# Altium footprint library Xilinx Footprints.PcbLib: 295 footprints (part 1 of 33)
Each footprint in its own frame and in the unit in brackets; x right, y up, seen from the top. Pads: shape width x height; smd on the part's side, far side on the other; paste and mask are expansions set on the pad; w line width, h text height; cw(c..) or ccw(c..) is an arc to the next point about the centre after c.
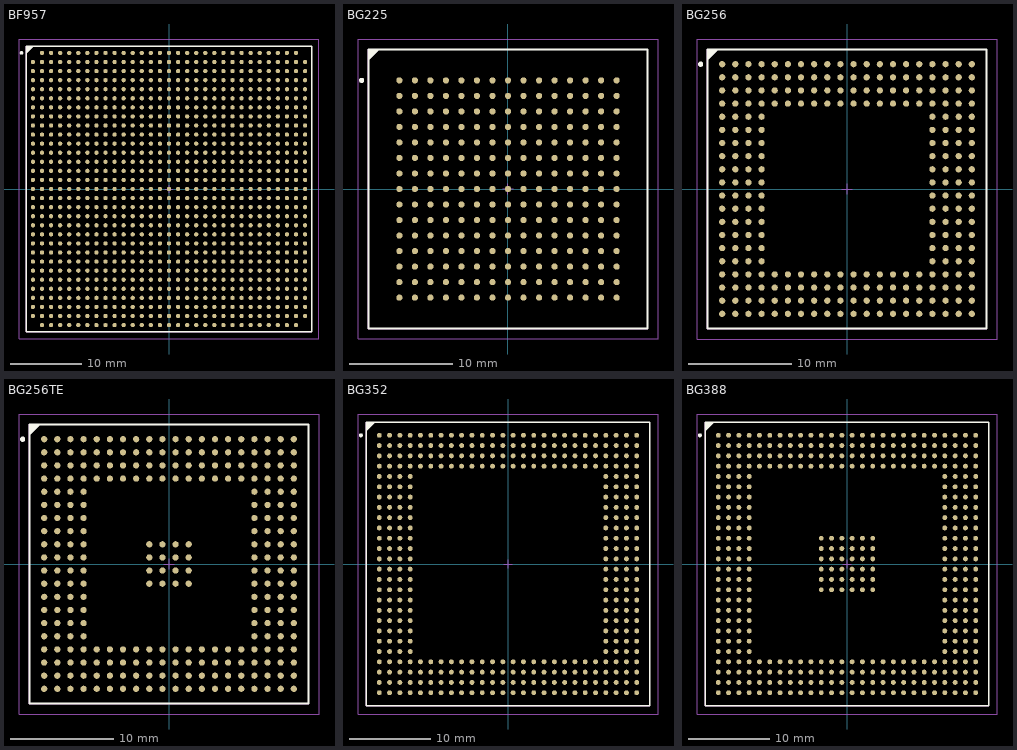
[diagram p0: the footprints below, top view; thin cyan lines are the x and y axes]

## BF957 [mm] "957-Ball Plastic Flip Chip Ball Grid Array (BF957)"
height 3.5
pads (957):
  round 0.6 smd: A2(-17.78,19.05) A3(-16.51,19.05) A4(-15.24,19.05) A5(-13.97,19.05) A6(-12.7,19.05) A7(-11.43,19.05) A8(-10.16,19.05) A9(-8.89,19.05) A10(-7.62,19.05) A11(-6.35,19.05) A12(-5.08,19.05) A13(-3.81,19.05) A14(-2.54,19.05) A15(-1.27,19.05) A16(0,19.05) A17(1.27,19.05) A18(2.54,19.05) A19(3.81,19.05) A20(5.08,19.05) A21(6.35,19.05) A22(7.62,19.05) A23(8.89,19.05) A24(10.16,19.05) A25(11.43,19.05) A26(12.7,19.05) A27(13.97,19.05) A28(15.24,19.05) A29(16.51,19.05) A30(17.78,19.05) AA1(-19.05,-6.35) AA2(-17.78,-6.35) AA3(-16.51,-6.35) AA4(-15.24,-6.35) AA5(-13.97,-6.35) AA6(-12.7,-6.35) AA7(-11.43,-6.35) AA8(-10.16,-6.35) AA9(-8.89,-6.35) AA10(-7.62,-6.35) AA11(-6.35,-6.35) AA12(-5.08,-6.35) AA13(-3.81,-6.35) AA14(-2.54,-6.35) AA15(-1.27,-6.35) AA16(0,-6.35) AA17(1.27,-6.35) AA18(2.54,-6.35) AA19(3.81,-6.35) AA20(5.08,-6.35) AA21(6.35,-6.35) AA22(7.62,-6.35) AA23(8.89,-6.35) AA24(10.16,-6.35) AA25(11.43,-6.35) AA26(12.7,-6.35) AA27(13.97,-6.35) AA28(15.24,-6.35) AA29(16.51,-6.35) AA30(17.78,-6.35) AA31(19.05,-6.35) AB1(-19.05,-7.62) AB2(-17.78,-7.62) AB3(-16.51,-7.62) AB4(-15.24,-7.62) AB5(-13.97,-7.62) AB6(-12.7,-7.62) AB7(-11.43,-7.62) AB8(-10.16,-7.62) AB9(-8.89,-7.62) AB10(-7.62,-7.62) AB11(-6.35,-7.62) AB12(-5.08,-7.62) AB13(-3.81,-7.62) AB14(-2.54,-7.62) AB15(-1.27,-7.62) AB16(0,-7.62) AB17(1.27,-7.62) AB18(2.54,-7.62) AB19(3.81,-7.62) AB20(5.08,-7.62) AB21(6.35,-7.62) AB22(7.62,-7.62) AB23(8.89,-7.62) AB24(10.16,-7.62) AB25(11.43,-7.62) AB26(12.7,-7.62) AB27(13.97,-7.62) AB28(15.24,-7.62) AB29(16.51,-7.62) AB30(17.78,-7.62) AB31(19.05,-7.62) AC1(-19.05,-8.89) AC2(-17.78,-8.89) AC3(-16.51,-8.89) AC4(-15.24,-8.89) AC5(-13.97,-8.89) AC6(-12.7,-8.89) AC7(-11.43,-8.89) AC8(-10.16,-8.89) AC9(-8.89,-8.89) AC10(-7.62,-8.89) AC11(-6.35,-8.89) AC12(-5.08,-8.89) AC13(-3.81,-8.89) AC14(-2.54,-8.89) AC15(-1.27,-8.89) AC16(0,-8.89) AC17(1.27,-8.89) AC18(2.54,-8.89) AC19(3.81,-8.89) AC20(5.08,-8.89) AC21(6.35,-8.89) AC22(7.62,-8.89) AC23(8.89,-8.89) AC24(10.16,-8.89) AC25(11.43,-8.89) AC26(12.7,-8.89) AC27(13.97,-8.89) AC28(15.24,-8.89) AC29(16.51,-8.89) AC30(17.78,-8.89) AC31(19.05,-8.89) AD1(-19.05,-10.16) AD2(-17.78,-10.16) AD3(-16.51,-10.16) AD4(-15.24,-10.16) AD5(-13.97,-10.16) AD6(-12.7,-10.16) AD7(-11.43,-10.16) AD8(-10.16,-10.16) AD9(-8.89,-10.16) AD10(-7.62,-10.16) AD11(-6.35,-10.16) AD12(-5.08,-10.16) AD13(-3.81,-10.16) AD14(-2.54,-10.16) AD15(-1.27,-10.16) AD16(0,-10.16) AD17(1.27,-10.16) AD18(2.54,-10.16) AD19(3.81,-10.16) AD20(5.08,-10.16) AD21(6.35,-10.16) AD22(7.62,-10.16) AD23(8.89,-10.16) AD24(10.16,-10.16) AD25(11.43,-10.16) AD26(12.7,-10.16) AD27(13.97,-10.16) AD28(15.24,-10.16) AD29(16.51,-10.16) AD30(17.78,-10.16) AD31(19.05,-10.16) AE1(-19.05,-11.43) AE2(-17.78,-11.43) AE3(-16.51,-11.43) AE4(-15.24,-11.43) AE5(-13.97,-11.43) AE6(-12.7,-11.43) AE7(-11.43,-11.43) AE8(-10.16,-11.43) AE9(-8.89,-11.43) AE10(-7.62,-11.43) AE11(-6.35,-11.43) AE12(-5.08,-11.43) AE13(-3.81,-11.43) AE14(-2.54,-11.43) AE15(-1.27,-11.43) AE16(0,-11.43) AE17(1.27,-11.43) AE18(2.54,-11.43) AE19(3.81,-11.43) AE20(5.08,-11.43) AE21(6.35,-11.43) AE22(7.62,-11.43) AE23(8.89,-11.43) AE24(10.16,-11.43) AE25(11.43,-11.43) AE26(12.7,-11.43) AE27(13.97,-11.43) AE28(15.24,-11.43) AE29(16.51,-11.43) AE30(17.78,-11.43) AE31(19.05,-11.43) AF1(-19.05,-12.7) AF2(-17.78,-12.7) AF3(-16.51,-12.7) AF4(-15.24,-12.7) AF5(-13.97,-12.7) AF6(-12.7,-12.7) AF7(-11.43,-12.7) AF8(-10.16,-12.7) AF9(-8.89,-12.7) AF10(-7.62,-12.7) AF11(-6.35,-12.7) AF12(-5.08,-12.7) AF13(-3.81,-12.7) AF14(-2.54,-12.7) AF15(-1.27,-12.7) AF16(0,-12.7) AF17(1.27,-12.7) AF18(2.54,-12.7) AF19(3.81,-12.7) AF20(5.08,-12.7) AF21(6.35,-12.7) AF22(7.62,-12.7) AF23(8.89,-12.7) AF24(10.16,-12.7) AF25(11.43,-12.7) AF26(12.7,-12.7) AF27(13.97,-12.7) AF28(15.24,-12.7) AF29(16.51,-12.7) AF30(17.78,-12.7) AF31(19.05,-12.7) AG1(-19.05,-13.97) AG2(-17.78,-13.97) AG3(-16.51,-13.97) AG4(-15.24,-13.97) AG5(-13.97,-13.97) AG6(-12.7,-13.97) AG7(-11.43,-13.97) AG8(-10.16,-13.97) AG9(-8.89,-13.97) AG10(-7.62,-13.97) AG11(-6.35,-13.97) AG12(-5.08,-13.97) AG13(-3.81,-13.97) AG14(-2.54,-13.97) AG15(-1.27,-13.97) AG16(0,-13.97) AG17(1.27,-13.97) AG18(2.54,-13.97) AG19(3.81,-13.97) AG20(5.08,-13.97) AG21(6.35,-13.97) AG22(7.62,-13.97) AG23(8.89,-13.97) AG24(10.16,-13.97) AG25(11.43,-13.97) AG26(12.7,-13.97) AG27(13.97,-13.97) AG28(15.24,-13.97) AG29(16.51,-13.97) AG30(17.78,-13.97) AG31(19.05,-13.97) AH1(-19.05,-15.24) AH2(-17.78,-15.24) AH3(-16.51,-15.24) AH4(-15.24,-15.24) AH5(-13.97,-15.24) AH6(-12.7,-15.24) AH7(-11.43,-15.24) AH8(-10.16,-15.24) AH9(-8.89,-15.24) AH10(-7.62,-15.24) AH11(-6.35,-15.24) AH12(-5.08,-15.24) AH13(-3.81,-15.24) AH14(-2.54,-15.24) AH15(-1.27,-15.24) AH16(0,-15.24) AH17(1.27,-15.24) AH18(2.54,-15.24) AH19(3.81,-15.24) AH20(5.08,-15.24) AH21(6.35,-15.24) AH22(7.62,-15.24) AH23(8.89,-15.24) AH24(10.16,-15.24) AH25(11.43,-15.24) AH26(12.7,-15.24) AH27(13.97,-15.24) AH28(15.24,-15.24) AH29(16.51,-15.24) AH30(17.78,-15.24) AH31(19.05,-15.24) AJ1(-19.05,-16.51) AJ2(-17.78,-16.51) AJ3(-16.51,-16.51) AJ4(-15.24,-16.51) AJ5(-13.97,-16.51) AJ6(-12.7,-16.51) AJ7(-11.43,-16.51) AJ8(-10.16,-16.51) AJ9(-8.89,-16.51) AJ10(-7.62,-16.51) AJ11(-6.35,-16.51) AJ12(-5.08,-16.51) AJ13(-3.81,-16.51) AJ14(-2.54,-16.51) AJ15(-1.27,-16.51) AJ16(0,-16.51) AJ17(1.27,-16.51) AJ18(2.54,-16.51) AJ19(3.81,-16.51) AJ20(5.08,-16.51) AJ21(6.35,-16.51) AJ22(7.62,-16.51) AJ23(8.89,-16.51) AJ24(10.16,-16.51) AJ25(11.43,-16.51) AJ26(12.7,-16.51) AJ27(13.97,-16.51) AJ28(15.24,-16.51) AJ29(16.51,-16.51) AJ30(17.78,-16.51) AJ31(19.05,-16.51) AK1(-19.05,-17.78) AK2(-17.78,-17.78) AK3(-16.51,-17.78) AK4(-15.24,-17.78) AK5(-13.97,-17.78) AK6(-12.7,-17.78) AK7(-11.43,-17.78) AK8(-10.16,-17.78) AK9(-8.89,-17.78) AK10(-7.62,-17.78) AK11(-6.35,-17.78) AK12(-5.08,-17.78) AK13(-3.81,-17.78) AK14(-2.54,-17.78) AK15(-1.27,-17.78) AK16(0,-17.78) AK17(1.27,-17.78) AK18(2.54,-17.78) AK19(3.81,-17.78) AK20(5.08,-17.78) AK21(6.35,-17.78) AK22(7.62,-17.78) AK23(8.89,-17.78) AK24(10.16,-17.78) AK25(11.43,-17.78) AK26(12.7,-17.78) AK27(13.97,-17.78) AK28(15.24,-17.78) AK29(16.51,-17.78) AK30(17.78,-17.78) AK31(19.05,-17.78) AL2(-17.78,-19.05) AL3(-16.51,-19.05) AL4(-15.24,-19.05) AL5(-13.97,-19.05) AL6(-12.7,-19.05) AL7(-11.43,-19.05) AL8(-10.16,-19.05) AL9(-8.89,-19.05) AL10(-7.62,-19.05) AL11(-6.35,-19.05) AL12(-5.08,-19.05) AL13(-3.81,-19.05) AL14(-2.54,-19.05) AL15(-1.27,-19.05) AL16(0,-19.05) AL17(1.27,-19.05) AL18(2.54,-19.05) AL19(3.81,-19.05) AL20(5.08,-19.05) AL21(6.35,-19.05) AL22(7.62,-19.05) AL23(8.89,-19.05) AL24(10.16,-19.05) AL25(11.43,-19.05) AL26(12.7,-19.05) AL27(13.97,-19.05) AL28(15.24,-19.05) AL29(16.51,-19.05) AL30(17.78,-19.05) B1(-19.05,17.78) B2(-17.78,17.78) B3(-16.51,17.78) B4(-15.24,17.78) B5(-13.97,17.78) B6(-12.7,17.78) B7(-11.43,17.78) B8(-10.16,17.78) B9(-8.89,17.78) B10(-7.62,17.78) B11(-6.35,17.78) B12(-5.08,17.78) B13(-3.81,17.78) B14(-2.54,17.78) B15(-1.27,17.78) B16(0,17.78) B17(1.27,17.78) B18(2.54,17.78) B19(3.81,17.78) B20(5.08,17.78) B21(6.35,17.78) B22(7.62,17.78) B23(8.89,17.78) B24(10.16,17.78) B25(11.43,17.78) B26(12.7,17.78) B27(13.97,17.78) B28(15.24,17.78) B29(16.51,17.78) B30(17.78,17.78) B31(19.05,17.78) C1(-19.05,16.51) C2(-17.78,16.51) C3(-16.51,16.51) C4(-15.24,16.51) C5(-13.97,16.51) C6(-12.7,16.51) C7(-11.43,16.51) C8(-10.16,16.51) C9(-8.89,16.51) C10(-7.62,16.51) C11(-6.35,16.51) C12(-5.08,16.51) C13(-3.81,16.51) C14(-2.54,16.51) C15(-1.27,16.51) C16(0,16.51) C17(1.27,16.51) C18(2.54,16.51) C19(3.81,16.51) C20(5.08,16.51) C21(6.35,16.51) C22(7.62,16.51) C23(8.89,16.51) C24(10.16,16.51) C25(11.43,16.51) C26(12.7,16.51) C27(13.97,16.51) C28(15.24,16.51) C29(16.51,16.51) C30(17.78,16.51) C31(19.05,16.51) D1(-19.05,15.24) D2(-17.78,15.24) D3(-16.51,15.24) D4(-15.24,15.24) D5(-13.97,15.24) D6(-12.7,15.24) D7(-11.43,15.24) D8(-10.16,15.24) D9(-8.89,15.24) D10(-7.62,15.24) D11(-6.35,15.24) D12(-5.08,15.24) D13(-3.81,15.24) D14(-2.54,15.24) D15(-1.27,15.24) D16(0,15.24) D17(1.27,15.24) D18(2.54,15.24) D19(3.81,15.24) D20(5.08,15.24) D21(6.35,15.24) D22(7.62,15.24) D23(8.89,15.24) D24(10.16,15.24) D25(11.43,15.24) D26(12.7,15.24) D27(13.97,15.24) D28(15.24,15.24) D29(16.51,15.24) D30(17.78,15.24) D31(19.05,15.24) E1(-19.05,13.97) E2(-17.78,13.97) E3(-16.51,13.97) E4(-15.24,13.97) E5(-13.97,13.97) E6(-12.7,13.97) E7(-11.43,13.97) E8(-10.16,13.97) E9(-8.89,13.97) E10(-7.62,13.97) E11(-6.35,13.97) E12(-5.08,13.97) E13(-3.81,13.97) E14(-2.54,13.97) E15(-1.27,13.97) E16(0,13.97) E17(1.27,13.97) E18(2.54,13.97) E19(3.81,13.97) E20(5.08,13.97) E21(6.35,13.97) E22(7.62,13.97) E23(8.89,13.97) E24(10.16,13.97) E25(11.43,13.97) E26(12.7,13.97) E27(13.97,13.97) E28(15.24,13.97) E29(16.51,13.97) E30(17.78,13.97) E31(19.05,13.97) F1(-19.05,12.7) F2(-17.78,12.7) F3(-16.51,12.7) F4(-15.24,12.7) F5(-13.97,12.7) F6(-12.7,12.7) F7(-11.43,12.7) F8(-10.16,12.7) F9(-8.89,12.7) F10(-7.62,12.7) F11(-6.35,12.7) F12(-5.08,12.7) F13(-3.81,12.7) F14(-2.54,12.7) F15(-1.27,12.7) F16(0,12.7) F17(1.27,12.7) F18(2.54,12.7) F19(3.81,12.7) F20(5.08,12.7) F21(6.35,12.7) F22(7.62,12.7) F23(8.89,12.7) F24(10.16,12.7) F25(11.43,12.7) F26(12.7,12.7) F27(13.97,12.7) F28(15.24,12.7) F29(16.51,12.7) F30(17.78,12.7) F31(19.05,12.7) G1(-19.05,11.43) G2(-17.78,11.43) G3(-16.51,11.43) G4(-15.24,11.43) G5(-13.97,11.43) G6(-12.7,11.43) G7(-11.43,11.43) G8(-10.16,11.43) G9(-8.89,11.43) G10(-7.62,11.43) G11(-6.35,11.43) G12(-5.08,11.43) G13(-3.81,11.43) G14(-2.54,11.43) G15(-1.27,11.43) G16(0,11.43) G17(1.27,11.43) G18(2.54,11.43) G19(3.81,11.43) G20(5.08,11.43) G21(6.35,11.43) G22(7.62,11.43) G23(8.89,11.43) G24(10.16,11.43) G25(11.43,11.43) G26(12.7,11.43) G27(13.97,11.43) G28(15.24,11.43) G29(16.51,11.43) G30(17.78,11.43) G31(19.05,11.43) H1(-19.05,10.16) H2(-17.78,10.16) H3(-16.51,10.16) H4(-15.24,10.16) H5(-13.97,10.16) H6(-12.7,10.16) H7(-11.43,10.16) H8(-10.16,10.16) H9(-8.89,10.16) H10(-7.62,10.16) H11(-6.35,10.16) H12(-5.08,10.16) H13(-3.81,10.16) H14(-2.54,10.16) H15(-1.27,10.16) H16(0,10.16) H17(1.27,10.16) H18(2.54,10.16) H19(3.81,10.16) H20(5.08,10.16) H21(6.35,10.16) H22(7.62,10.16) H23(8.89,10.16) H24(10.16,10.16) H25(11.43,10.16) H26(12.7,10.16) H27(13.97,10.16) H28(15.24,10.16) H29(16.51,10.16) H30(17.78,10.16) H31(19.05,10.16) J1(-19.05,8.89) J2(-17.78,8.89) J3(-16.51,8.89) J4(-15.24,8.89) J5(-13.97,8.89) J6(-12.7,8.89) J7(-11.43,8.89) J8(-10.16,8.89) J9(-8.89,8.89) J10(-7.62,8.89) J11(-6.35,8.89) J12(-5.08,8.89) J13(-3.81,8.89) J14(-2.54,8.89) J15(-1.27,8.89) J16(0,8.89) J17(1.27,8.89) J18(2.54,8.89) J19(3.81,8.89) J20(5.08,8.89) J21(6.35,8.89) J22(7.62,8.89) J23(8.89,8.89) J24(10.16,8.89) J25(11.43,8.89) J26(12.7,8.89) J27(13.97,8.89) J28(15.24,8.89) J29(16.51,8.89) J30(17.78,8.89) J31(19.05,8.89) K1(-19.05,7.62) K2(-17.78,7.62) K3(-16.51,7.62) K4(-15.24,7.62) K5(-13.97,7.62) K6(-12.7,7.62) K7(-11.43,7.62) K8(-10.16,7.62) K9(-8.89,7.62) K10(-7.62,7.62) K11(-6.35,7.62) K12(-5.08,7.62) K13(-3.81,7.62) K14(-2.54,7.62) K15(-1.27,7.62) K16(0,7.62) K17(1.27,7.62) K18(2.54,7.62) K19(3.81,7.62) K20(5.08,7.62) K21(6.35,7.62) K22(7.62,7.62) K23(8.89,7.62) K24(10.16,7.62) K25(11.43,7.62) K26(12.7,7.62) K27(13.97,7.62) K28(15.24,7.62) K29(16.51,7.62) K30(17.78,7.62) K31(19.05,7.62) L1(-19.05,6.35) L2(-17.78,6.35) L3(-16.51,6.35) L4(-15.24,6.35) L5(-13.97,6.35) L6(-12.7,6.35) L7(-11.43,6.35) L8(-10.16,6.35) L9(-8.89,6.35) L10(-7.62,6.35) L11(-6.35,6.35) L12(-5.08,6.35) L13(-3.81,6.35) L14(-2.54,6.35) L15(-1.27,6.35) L16(0,6.35) L17(1.27,6.35) L18(2.54,6.35) L19(3.81,6.35) L20(5.08,6.35) L21(6.35,6.35) L22(7.62,6.35) L23(8.89,6.35) L24(10.16,6.35) L25(11.43,6.35) L26(12.7,6.35) L27(13.97,6.35) L28(15.24,6.35) L29(16.51,6.35) L30(17.78,6.35) L31(19.05,6.35) M1(-19.05,5.08) M2(-17.78,5.08) M3(-16.51,5.08) M4(-15.24,5.08) M5(-13.97,5.08) M6(-12.7,5.08) M7(-11.43,5.08) M8(-10.16,5.08) M9(-8.89,5.08) M10(-7.62,5.08) M11(-6.35,5.08) M12(-5.08,5.08) M13(-3.81,5.08) M14(-2.54,5.08) M15(-1.27,5.08) M16(0,5.08) M17(1.27,5.08) M18(2.54,5.08) M19(3.81,5.08) M20(5.08,5.08) M21(6.35,5.08) M22(7.62,5.08) M23(8.89,5.08) M24(10.16,5.08) M25(11.43,5.08) M26(12.7,5.08) M27(13.97,5.08) M28(15.24,5.08) M29(16.51,5.08) M30(17.78,5.08) M31(19.05,5.08) N1(-19.05,3.81) N2(-17.78,3.81) N3(-16.51,3.81) N4(-15.24,3.81) N5(-13.97,3.81) N6(-12.7,3.81) N7(-11.43,3.81) N8(-10.16,3.81) N9(-8.89,3.81) N10(-7.62,3.81) N11(-6.35,3.81) N12(-5.08,3.81) N13(-3.81,3.81) N14(-2.54,3.81) N15(-1.27,3.81) N16(0,3.81) N17(1.27,3.81) N18(2.54,3.81) N19(3.81,3.81) N20(5.08,3.81) N21(6.35,3.81) N22(7.62,3.81) N23(8.89,3.81) N24(10.16,3.81) N25(11.43,3.81) N26(12.7,3.81) N27(13.97,3.81) N28(15.24,3.81) N29(16.51,3.81) N30(17.78,3.81) N31(19.05,3.81) P1(-19.05,2.54) P2(-17.78,2.54) P3(-16.51,2.54) P4(-15.24,2.54) P5(-13.97,2.54) P6(-12.7,2.54) P7(-11.43,2.54) P8(-10.16,2.54) P9(-8.89,2.54) P10(-7.62,2.54) P11(-6.35,2.54) P12(-5.08,2.54) P13(-3.81,2.54) P14(-2.54,2.54) P15(-1.27,2.54) P16(0,2.54) P17(1.27,2.54) P18(2.54,2.54) P19(3.81,2.54) P20(5.08,2.54) P21(6.35,2.54) P22(7.62,2.54) P23(8.89,2.54) P24(10.16,2.54) P25(11.43,2.54) P26(12.7,2.54) P27(13.97,2.54) P28(15.24,2.54) P29(16.51,2.54) P30(17.78,2.54) P31(19.05,2.54) R1(-19.05,1.27) R2(-17.78,1.27) R3(-16.51,1.27) R4(-15.24,1.27) R5(-13.97,1.27) R6(-12.7,1.27) R7(-11.43,1.27) R8(-10.16,1.27) R9(-8.89,1.27) R10(-7.62,1.27) R11(-6.35,1.27) R12(-5.08,1.27) R13(-3.81,1.27) R14(-2.54,1.27) R15(-1.27,1.27) R16(0,1.27) R17(1.27,1.27) R18(2.54,1.27) R19(3.81,1.27) R20(5.08,1.27) R21(6.35,1.27) R22(7.62,1.27) R23(8.89,1.27) R24(10.16,1.27) R25(11.43,1.27) R26(12.7,1.27) R27(13.97,1.27) R28(15.24,1.27) R29(16.51,1.27) R30(17.78,1.27) R31(19.05,1.27) T1(-19.05,0) T2(-17.78,0) T3(-16.51,0) T4(-15.24,0) T5(-13.97,0) T6(-12.7,0) T7(-11.43,0) T8(-10.16,0) T9(-8.89,0) T10(-7.62,0) T11(-6.35,0) T12(-5.08,0) T13(-3.81,0) T14(-2.54,0) T15(-1.27,0) T16(0,0) T17(1.27,0) T18(2.54,0) T19(3.81,0) T20(5.08,0) T21(6.35,0) T22(7.62,0) T23(8.89,0) T24(10.16,0) T25(11.43,0) T26(12.7,0) T27(13.97,0) T28(15.24,0) T29(16.51,0) T30(17.78,0) T31(19.05,0) U1(-19.05,-1.27) U2(-17.78,-1.27) U3(-16.51,-1.27) U4(-15.24,-1.27) U5(-13.97,-1.27) U6(-12.7,-1.27) U7(-11.43,-1.27) U8(-10.16,-1.27) U9(-8.89,-1.27) U10(-7.62,-1.27) U11(-6.35,-1.27) U12(-5.08,-1.27) U13(-3.81,-1.27) U14(-2.54,-1.27) U15(-1.27,-1.27) U16(0,-1.27) U17(1.27,-1.27) U18(2.54,-1.27) U19(3.81,-1.27) U20(5.08,-1.27) U21(6.35,-1.27) U22(7.62,-1.27) U23(8.89,-1.27) U24(10.16,-1.27) U25(11.43,-1.27) U26(12.7,-1.27) U27(13.97,-1.27) U28(15.24,-1.27) U29(16.51,-1.27) U30(17.78,-1.27) U31(19.05,-1.27) V1(-19.05,-2.54) V2(-17.78,-2.54) V3(-16.51,-2.54) V4(-15.24,-2.54) V5(-13.97,-2.54) V6(-12.7,-2.54) V7(-11.43,-2.54) V8(-10.16,-2.54) V9(-8.89,-2.54) V10(-7.62,-2.54) V11(-6.35,-2.54) V12(-5.08,-2.54) V13(-3.81,-2.54) V14(-2.54,-2.54) V15(-1.27,-2.54) V16(0,-2.54) V17(1.27,-2.54) V18(2.54,-2.54) V19(3.81,-2.54) V20(5.08,-2.54) V21(6.35,-2.54) V22(7.62,-2.54) V23(8.89,-2.54) V24(10.16,-2.54) V25(11.43,-2.54) V26(12.7,-2.54) V27(13.97,-2.54) V28(15.24,-2.54) V29(16.51,-2.54) V30(17.78,-2.54) V31(19.05,-2.54) W1(-19.05,-3.81) W2(-17.78,-3.81) W3(-16.51,-3.81) W4(-15.24,-3.81) W5(-13.97,-3.81) W6(-12.7,-3.81) W7(-11.43,-3.81) W8(-10.16,-3.81) W9(-8.89,-3.81) W10(-7.62,-3.81) W11(-6.35,-3.81) W12(-5.08,-3.81) W13(-3.81,-3.81) W14(-2.54,-3.81) W15(-1.27,-3.81) W16(0,-3.81) W17(1.27,-3.81) W18(2.54,-3.81) W19(3.81,-3.81) W20(5.08,-3.81) W21(6.35,-3.81) W22(7.62,-3.81) W23(8.89,-3.81) W24(10.16,-3.81) W25(11.43,-3.81) W26(12.7,-3.81) W27(13.97,-3.81) W28(15.24,-3.81) W29(16.51,-3.81) W30(17.78,-3.81) W31(19.05,-3.81) Y1(-19.05,-5.08) Y2(-17.78,-5.08) Y3(-16.51,-5.08) Y4(-15.24,-5.08) Y5(-13.97,-5.08) Y6(-12.7,-5.08) Y7(-11.43,-5.08) Y8(-10.16,-5.08) Y9(-8.89,-5.08) Y10(-7.62,-5.08) Y11(-6.35,-5.08) Y12(-5.08,-5.08) Y13(-3.81,-5.08) Y14(-2.54,-5.08) Y15(-1.27,-5.08) Y16(0,-5.08) Y17(1.27,-5.08) Y18(2.54,-5.08) Y19(3.81,-5.08) Y20(5.08,-5.08) Y21(6.35,-5.08) Y22(7.62,-5.08) Y23(8.89,-5.08) Y24(10.16,-5.08) Y25(11.43,-5.08) Y26(12.7,-5.08) Y27(13.97,-5.08) Y28(15.24,-5.08) Y29(16.51,-5.08) Y30(17.78,-5.08) Y31(19.05,-5.08)
Top Overlay:
  circle w0.25: c-20.65,19.05 r0.125
  region: -19.09,20 -20,19.09 -20,20
  lines w0.2: -20,19.09 -19.09,20 ; -20,-20 20,-20 20,20 -20,20 -20,-20
Mechanical 13:
  lines w0.1: -20,-20 20,-20 20,20 -20,20 -20,-20
Mechanical 15:
  lines w0.1: -0.5,0 0.5,0 ; 0,-0.5 0,0.5 ; -21,-21 21,-21 21,21 -21,21 -21,-21
3D body: height 3.5, standoff 0, extent -20,-20 20,20

## BG225 [mm] "225-Ball Plastic Ball Grid Array (BG225)"
height 2.3
pads (225):
  round 0.6 smd: A1(-10.5,10.5) A2(-9,10.5) A3(-7.5,10.5) A4(-6,10.5) A5(-4.5,10.5) A6(-3,10.5) A7(-1.5,10.5) A8(0,10.5) A9(1.5,10.5) A10(3,10.5) A11(4.5,10.5) A12(6,10.5) A13(7.5,10.5) A14(9,10.5) A15(10.5,10.5) B1(-10.5,9) B2(-9,9) B3(-7.5,9) B4(-6,9) B5(-4.5,9) B6(-3,9) B7(-1.5,9) B8(0,9) B9(1.5,9) B10(3,9) B11(4.5,9) B12(6,9) B13(7.5,9) B14(9,9) B15(10.5,9) C1(-10.5,7.5) C2(-9,7.5) C3(-7.5,7.5) C4(-6,7.5) C5(-4.5,7.5) C6(-3,7.5) C7(-1.5,7.5) C8(0,7.5) C9(1.5,7.5) C10(3,7.5) C11(4.5,7.5) C12(6,7.5) C13(7.5,7.5) C14(9,7.5) C15(10.5,7.5) D1(-10.5,6) D2(-9,6) D3(-7.5,6) D4(-6,6) D5(-4.5,6) D6(-3,6) D7(-1.5,6) D8(0,6) D9(1.5,6) D10(3,6) D11(4.5,6) D12(6,6) D13(7.5,6) D14(9,6) D15(10.5,6) E1(-10.5,4.5) E2(-9,4.5) E3(-7.5,4.5) E4(-6,4.5) E5(-4.5,4.5) E6(-3,4.5) E7(-1.5,4.5) E8(0,4.5) E9(1.5,4.5) E10(3,4.5) E11(4.5,4.5) E12(6,4.5) E13(7.5,4.5) E14(9,4.5) E15(10.5,4.5) F1(-10.5,3) F2(-9,3) F3(-7.5,3) F4(-6,3) F5(-4.5,3) F6(-3,3) F7(-1.5,3) F8(0,3) F9(1.5,3) F10(3,3) F11(4.5,3) F12(6,3) F13(7.5,3) F14(9,3) F15(10.5,3) G1(-10.5,1.5) G2(-9,1.5) G3(-7.5,1.5) G4(-6,1.5) G5(-4.5,1.5) G6(-3,1.5) G7(-1.5,1.5) G8(0,1.5) G9(1.5,1.5) G10(3,1.5) G11(4.5,1.5) G12(6,1.5) G13(7.5,1.5) G14(9,1.5) G15(10.5,1.5) H1(-10.5,0) H2(-9,0) H3(-7.5,0) H4(-6,0) H5(-4.5,0) H6(-3,0) H7(-1.5,0) H8(0,0) H9(1.5,0) H10(3,0) H11(4.5,0) H12(6,0) H13(7.5,0) H14(9,0) H15(10.5,0) J1(-10.5,-1.5) J2(-9,-1.5) J3(-7.5,-1.5) J4(-6,-1.5) J5(-4.5,-1.5) J6(-3,-1.5) J7(-1.5,-1.5) J8(0,-1.5) J9(1.5,-1.5) J10(3,-1.5) J11(4.5,-1.5) J12(6,-1.5) J13(7.5,-1.5) J14(9,-1.5) J15(10.5,-1.5) K1(-10.5,-3) K2(-9,-3) K3(-7.5,-3) K4(-6,-3) K5(-4.5,-3) K6(-3,-3) K7(-1.5,-3) K8(0,-3) K9(1.5,-3) K10(3,-3) K11(4.5,-3) K12(6,-3) K13(7.5,-3) K14(9,-3) K15(10.5,-3) L1(-10.5,-4.5) L2(-9,-4.5) L3(-7.5,-4.5) L4(-6,-4.5) L5(-4.5,-4.5) L6(-3,-4.5) L7(-1.5,-4.5) L8(0,-4.5) L9(1.5,-4.5) L10(3,-4.5) L11(4.5,-4.5) L12(6,-4.5) L13(7.5,-4.5) L14(9,-4.5) L15(10.5,-4.5) M1(-10.5,-6) M2(-9,-6) M3(-7.5,-6) M4(-6,-6) M5(-4.5,-6) M6(-3,-6) M7(-1.5,-6) M8(0,-6) M9(1.5,-6) M10(3,-6) M11(4.5,-6) M12(6,-6) M13(7.5,-6) M14(9,-6) M15(10.5,-6) N1(-10.5,-7.5) N2(-9,-7.5) N3(-7.5,-7.5) N4(-6,-7.5) N5(-4.5,-7.5) N6(-3,-7.5) N7(-1.5,-7.5) N8(0,-7.5) N9(1.5,-7.5) N10(3,-7.5) N11(4.5,-7.5) N12(6,-7.5) N13(7.5,-7.5) N14(9,-7.5) N15(10.5,-7.5) P1(-10.5,-9) P2(-9,-9) P3(-7.5,-9) P4(-6,-9) P5(-4.5,-9) P6(-3,-9) P7(-1.5,-9) P8(0,-9) P9(1.5,-9) P10(3,-9) P11(4.5,-9) P12(6,-9) P13(7.5,-9) P14(9,-9) P15(10.5,-9) R1(-10.5,-10.5) R2(-9,-10.5) R3(-7.5,-10.5) R4(-6,-10.5) R5(-4.5,-10.5) R6(-3,-10.5) R7(-1.5,-10.5) R8(0,-10.5) R9(1.5,-10.5) R10(3,-10.5) R11(4.5,-10.5) R12(6,-10.5) R13(7.5,-10.5) R14(9,-10.5) R15(10.5,-10.5)
Top Overlay:
  circle w0.25: c-14.15,10.5 r0.125
  region: -12.5,13.5 -13.5,12.5 -13.5,13.5
  lines w0.2: -13.5,12.5 -12.5,13.5 ; -13.5,-13.5 13.5,-13.5 13.5,13.5 -13.5,13.5 -13.5,-13.5
Mechanical 13:
  lines w0.1: -13.5,-13.5 13.5,-13.5 13.5,13.5 -13.5,13.5 -13.5,-13.5
Mechanical 15:
  lines w0.1: -0.5,0 0.5,0 ; 0,-0.5 0,0.5 ; -14.5,-14.5 14.5,-14.5 14.5,14.5 -14.5,14.5 -14.5,-14.5
3D body: height 2.3, standoff 0, extent -13.5,-13.5 13.5,13.5

## BG256 [mm] "256-Ball Plastic Ball Grid Array (BG256)"
height 2.55
pads (256):
  round 0.6 smd: A1(-12.065,12.065) A2(-10.795,12.065) A3(-9.525,12.065) A4(-8.255,12.065) A5(-6.985,12.065) A6(-5.715,12.065) A7(-4.445,12.065) A8(-3.175,12.065) A9(-1.905,12.065) A10(-0.635,12.065) A11(0.635,12.065) A12(1.905,12.065) A13(3.175,12.065) A14(4.445,12.065) A15(5.715,12.065) A16(6.985,12.065) A17(8.255,12.065) A18(9.525,12.065) A19(10.795,12.065) A20(12.065,12.065) B1(-12.065,10.795) B2(-10.795,10.795) B3(-9.525,10.795) B4(-8.255,10.795) B5(-6.985,10.795) B6(-5.715,10.795) B7(-4.445,10.795) B8(-3.175,10.795) B9(-1.905,10.795) B10(-0.635,10.795) B11(0.635,10.795) B12(1.905,10.795) B13(3.175,10.795) B14(4.445,10.795) B15(5.715,10.795) B16(6.985,10.795) B17(8.255,10.795) B18(9.525,10.795) B19(10.795,10.795) B20(12.065,10.795) C1(-12.065,9.525) C2(-10.795,9.525) C3(-9.525,9.525) C4(-8.255,9.525) C5(-6.985,9.525) C6(-5.715,9.525) C7(-4.445,9.525) C8(-3.175,9.525) C9(-1.905,9.525) C10(-0.635,9.525) C11(0.635,9.525) C12(1.905,9.525) C13(3.175,9.525) C14(4.445,9.525) C15(5.715,9.525) C16(6.985,9.525) C17(8.255,9.525) C18(9.525,9.525) C19(10.795,9.525) C20(12.065,9.525) D1(-12.065,8.255) D2(-10.795,8.255) D3(-9.525,8.255) D4(-8.255,8.255) D5(-6.985,8.255) D6(-5.715,8.255) D7(-4.445,8.255) D8(-3.175,8.255) D9(-1.905,8.255) D10(-0.635,8.255) D11(0.635,8.255) D12(1.905,8.255) D13(3.175,8.255) D14(4.445,8.255) D15(5.715,8.255) D16(6.985,8.255) D17(8.255,8.255) D18(9.525,8.255) D19(10.795,8.255) D20(12.065,8.255) E1(-12.065,6.985) E2(-10.795,6.985) E3(-9.525,6.985) E4(-8.255,6.985) E17(8.255,6.985) E18(9.525,6.985) E19(10.795,6.985) E20(12.065,6.985) F1(-12.065,5.715) F2(-10.795,5.715) F3(-9.525,5.715) F4(-8.255,5.715) F17(8.255,5.715) F18(9.525,5.715) F19(10.795,5.715) F20(12.065,5.715) G1(-12.065,4.445) G2(-10.795,4.445) G3(-9.525,4.445) G4(-8.255,4.445) G17(8.255,4.445) G18(9.525,4.445) G19(10.795,4.445) G20(12.065,4.445) H1(-12.065,3.175) H2(-10.795,3.175) H3(-9.525,3.175) H4(-8.255,3.175) H17(8.255,3.175) H18(9.525,3.175) H19(10.795,3.175) H20(12.065,3.175) J1(-12.065,1.905) J2(-10.795,1.905) J3(-9.525,1.905) J4(-8.255,1.905) J17(8.255,1.905) J18(9.525,1.905) J19(10.795,1.905) J20(12.065,1.905) K1(-12.065,0.635) K2(-10.795,0.635) K3(-9.525,0.635) K4(-8.255,0.635) K17(8.255,0.635) K18(9.525,0.635) K19(10.795,0.635) K20(12.065,0.635) L1(-12.065,-0.635) L2(-10.795,-0.635) L3(-9.525,-0.635) L4(-8.255,-0.635) L17(8.255,-0.635) L18(9.525,-0.635) L19(10.795,-0.635) L20(12.065,-0.635) M1(-12.065,-1.905) M2(-10.795,-1.905) M3(-9.525,-1.905) M4(-8.255,-1.905) M17(8.255,-1.905) M18(9.525,-1.905) M19(10.795,-1.905) M20(12.065,-1.905) N1(-12.065,-3.175) N2(-10.795,-3.175) N3(-9.525,-3.175) N4(-8.255,-3.175) N17(8.255,-3.175) N18(9.525,-3.175) N19(10.795,-3.175) N20(12.065,-3.175) P1(-12.065,-4.445) P2(-10.795,-4.445) P3(-9.525,-4.445) P4(-8.255,-4.445) P17(8.255,-4.445) P18(9.525,-4.445) P19(10.795,-4.445) P20(12.065,-4.445) R1(-12.065,-5.715) R2(-10.795,-5.715) R3(-9.525,-5.715) R4(-8.255,-5.715) R17(8.255,-5.715) R18(9.525,-5.715) R19(10.795,-5.715) R20(12.065,-5.715) T1(-12.065,-6.985) T2(-10.795,-6.985) T3(-9.525,-6.985) T4(-8.255,-6.985) T17(8.255,-6.985) T18(9.525,-6.985) T19(10.795,-6.985) T20(12.065,-6.985) U1(-12.065,-8.255) U2(-10.795,-8.255) U3(-9.525,-8.255) U4(-8.255,-8.255) U5(-6.985,-8.255) U6(-5.715,-8.255) U7(-4.445,-8.255) U8(-3.175,-8.255) U9(-1.905,-8.255) U10(-0.635,-8.255) U11(0.635,-8.255) U12(1.905,-8.255) U13(3.175,-8.255) U14(4.445,-8.255) U15(5.715,-8.255) U16(6.985,-8.255) U17(8.255,-8.255) U18(9.525,-8.255) U19(10.795,-8.255) U20(12.065,-8.255) V1(-12.065,-9.525) V2(-10.795,-9.525) V3(-9.525,-9.525) V4(-8.255,-9.525) V5(-6.985,-9.525) V6(-5.715,-9.525) V7(-4.445,-9.525) V8(-3.175,-9.525) V9(-1.905,-9.525) V10(-0.635,-9.525) V11(0.635,-9.525) V12(1.905,-9.525) V13(3.175,-9.525) V14(4.445,-9.525) V15(5.715,-9.525) V16(6.985,-9.525) V17(8.255,-9.525) V18(9.525,-9.525) V19(10.795,-9.525) V20(12.065,-9.525) W1(-12.065,-10.795) W2(-10.795,-10.795) W3(-9.525,-10.795) W4(-8.255,-10.795) W5(-6.985,-10.795) W6(-5.715,-10.795) W7(-4.445,-10.795) W8(-3.175,-10.795) W9(-1.905,-10.795) W10(-0.635,-10.795) W11(0.635,-10.795) W12(1.905,-10.795) W13(3.175,-10.795) W14(4.445,-10.795) W15(5.715,-10.795) W16(6.985,-10.795) W17(8.255,-10.795) W18(9.525,-10.795) W19(10.795,-10.795) W20(12.065,-10.795) Y1(-12.065,-12.065) Y2(-10.795,-12.065) Y3(-9.525,-12.065) Y4(-8.255,-12.065) Y5(-6.985,-12.065) Y6(-5.715,-12.065) Y7(-4.445,-12.065) Y8(-3.175,-12.065) Y9(-1.905,-12.065) Y10(-0.635,-12.065) Y11(0.635,-12.065) Y12(1.905,-12.065) Y13(3.175,-12.065) Y14(4.445,-12.065) Y15(5.715,-12.065) Y16(6.985,-12.065) Y17(8.255,-12.065) Y18(9.525,-12.065) Y19(10.795,-12.065) Y20(12.065,-12.065)
Top Overlay:
  circle w0.25: c-14.15,12.065 r0.125
  region: -12.5,13.5 -13.5,12.5 -13.5,13.5
  lines w0.2: -13.5,12.5 -12.5,13.5 ; -13.5,-13.5 -13.5,13.5 13.5,13.5 13.5,-13.5 -13.5,-13.5
Mechanical 13:
  lines w0.1: -13.5,-13.5 -13.5,13.5 13.5,13.5 13.5,-13.5 -13.5,-13.5
Mechanical 15:
  lines w0.1: -0.5,0 0.5,0 ; 0,-0.5 0,0.5 ; -14.5,-14.5 -14.5,14.5 14.5,14.5 14.5,-14.5 -14.5,-14.5
3D body: height 2.55, standoff 0, extent -13.5,-13.5 13.5,13.5

## BG256TE [mm] "256-Ball Plastic Ball Grid Array (BG256) - Thermally Enhanced"
height 2.55
pads (272):
  round 0.6 smd: A1(-12.065,12.065) A2(-10.795,12.065) A3(-9.525,12.065) A4(-8.255,12.065) A5(-6.985,12.065) A6(-5.715,12.065) A7(-4.445,12.065) A8(-3.175,12.065) A9(-1.905,12.065) A10(-0.635,12.065) A11(0.635,12.065) A12(1.905,12.065) A13(3.175,12.065) A14(4.445,12.065) A15(5.715,12.065) A16(6.985,12.065) A17(8.255,12.065) A18(9.525,12.065) A19(10.795,12.065) A20(12.065,12.065) B1(-12.065,10.795) B2(-10.795,10.795) B3(-9.525,10.795) B4(-8.255,10.795) B5(-6.985,10.795) B6(-5.715,10.795) B7(-4.445,10.795) B8(-3.175,10.795) B9(-1.905,10.795) B10(-0.635,10.795) B11(0.635,10.795) B12(1.905,10.795) B13(3.175,10.795) B14(4.445,10.795) B15(5.715,10.795) B16(6.985,10.795) B17(8.255,10.795) B18(9.525,10.795) B19(10.795,10.795) B20(12.065,10.795) C1(-12.065,9.525) C2(-10.795,9.525) C3(-9.525,9.525) C4(-8.255,9.525) C5(-6.985,9.525) C6(-5.715,9.525) C7(-4.445,9.525) C8(-3.175,9.525) C9(-1.905,9.525) C10(-0.635,9.525) C11(0.635,9.525) C12(1.905,9.525) C13(3.175,9.525) C14(4.445,9.525) C15(5.715,9.525) C16(6.985,9.525) C17(8.255,9.525) C18(9.525,9.525) C19(10.795,9.525) C20(12.065,9.525) D1(-12.065,8.255) D2(-10.795,8.255) D3(-9.525,8.255) D4(-8.255,8.255) D5(-6.985,8.255) D6(-5.715,8.255) D7(-4.445,8.255) D8(-3.175,8.255) D9(-1.905,8.255) D10(-0.635,8.255) D11(0.635,8.255) D12(1.905,8.255) D13(3.175,8.255) D14(4.445,8.255) D15(5.715,8.255) D16(6.985,8.255) D17(8.255,8.255) D18(9.525,8.255) D19(10.795,8.255) D20(12.065,8.255) E1(-12.065,6.985) E2(-10.795,6.985) E3(-9.525,6.985) E4(-8.255,6.985) E17(8.255,6.985) E18(9.525,6.985) E19(10.795,6.985) E20(12.065,6.985) F1(-12.065,5.715) F2(-10.795,5.715) F3(-9.525,5.715) F4(-8.255,5.715) F17(8.255,5.715) F18(9.525,5.715) F19(10.795,5.715) F20(12.065,5.715) G1(-12.065,4.445) G2(-10.795,4.445) G3(-9.525,4.445) G4(-8.255,4.445) G17(8.255,4.445) G18(9.525,4.445) G19(10.795,4.445) G20(12.065,4.445) H1(-12.065,3.175) H2(-10.795,3.175) H3(-9.525,3.175) H4(-8.255,3.175) H17(8.255,3.175) H18(9.525,3.175) H19(10.795,3.175) H20(12.065,3.175) J1(-12.065,1.905) J2(-10.795,1.905) J3(-9.525,1.905) J4(-8.255,1.905) J9(-1.905,1.905) J10(-0.635,1.905) J11(0.635,1.905) J12(1.905,1.905) J17(8.255,1.905) J18(9.525,1.905) J19(10.795,1.905) J20(12.065,1.905) K1(-12.065,0.635) K2(-10.795,0.635) K3(-9.525,0.635) K4(-8.255,0.635) K9(-1.905,0.635) K10(-0.635,0.635) K11(0.635,0.635) K12(1.905,0.635) K17(8.255,0.635) K18(9.525,0.635) K19(10.795,0.635) K20(12.065,0.635) L1(-12.065,-0.635) L2(-10.795,-0.635) L3(-9.525,-0.635) L4(-8.255,-0.635) L9(-1.905,-0.635) L10(-0.635,-0.635) L11(0.635,-0.635) L12(1.905,-0.635) L17(8.255,-0.635) L18(9.525,-0.635) L19(10.795,-0.635) L20(12.065,-0.635) M1(-12.065,-1.905) M2(-10.795,-1.905) M3(-9.525,-1.905) M4(-8.255,-1.905) M9(-1.905,-1.905) M10(-0.635,-1.905) M11(0.635,-1.905) M12(1.905,-1.905) M17(8.255,-1.905) M18(9.525,-1.905) M19(10.795,-1.905) M20(12.065,-1.905) N1(-12.065,-3.175) N2(-10.795,-3.175) N3(-9.525,-3.175) N4(-8.255,-3.175) N17(8.255,-3.175) N18(9.525,-3.175) N19(10.795,-3.175) N20(12.065,-3.175) P1(-12.065,-4.445) P2(-10.795,-4.445) P3(-9.525,-4.445) P4(-8.255,-4.445) P17(8.255,-4.445) P18(9.525,-4.445) P19(10.795,-4.445) P20(12.065,-4.445) R1(-12.065,-5.715) R2(-10.795,-5.715) R3(-9.525,-5.715) R4(-8.255,-5.715) R17(8.255,-5.715) R18(9.525,-5.715) R19(10.795,-5.715) R20(12.065,-5.715) T1(-12.065,-6.985) T2(-10.795,-6.985) T3(-9.525,-6.985) T4(-8.255,-6.985) T17(8.255,-6.985) T18(9.525,-6.985) T19(10.795,-6.985) T20(12.065,-6.985) U1(-12.065,-8.255) U2(-10.795,-8.255) U3(-9.525,-8.255) U4(-8.255,-8.255) U5(-6.985,-8.255) U6(-5.715,-8.255) U7(-4.445,-8.255) U8(-3.175,-8.255) U9(-1.905,-8.255) U10(-0.635,-8.255) U11(0.635,-8.255) U12(1.905,-8.255) U13(3.175,-8.255) U14(4.445,-8.255) U15(5.715,-8.255) U16(6.985,-8.255) U17(8.255,-8.255) U18(9.525,-8.255) U19(10.795,-8.255) U20(12.065,-8.255) V1(-12.065,-9.525) V2(-10.795,-9.525) V3(-9.525,-9.525) V4(-8.255,-9.525) V5(-6.985,-9.525) V6(-5.715,-9.525) V7(-4.445,-9.525) V8(-3.175,-9.525) V9(-1.905,-9.525) V10(-0.635,-9.525) V11(0.635,-9.525) V12(1.905,-9.525) V13(3.175,-9.525) V14(4.445,-9.525) V15(5.715,-9.525) V16(6.985,-9.525) V17(8.255,-9.525) V18(9.525,-9.525) V19(10.795,-9.525) V20(12.065,-9.525) W1(-12.065,-10.795) W2(-10.795,-10.795) W3(-9.525,-10.795) W4(-8.255,-10.795) W5(-6.985,-10.795) W6(-5.715,-10.795) W7(-4.445,-10.795) W8(-3.175,-10.795) W9(-1.905,-10.795) W10(-0.635,-10.795) W11(0.635,-10.795) W12(1.905,-10.795) W13(3.175,-10.795) W14(4.445,-10.795) W15(5.715,-10.795) W16(6.985,-10.795) W17(8.255,-10.795) W18(9.525,-10.795) W19(10.795,-10.795) W20(12.065,-10.795) Y1(-12.065,-12.065) Y2(-10.795,-12.065) Y3(-9.525,-12.065) Y4(-8.255,-12.065) Y5(-6.985,-12.065) Y6(-5.715,-12.065) Y7(-4.445,-12.065) Y8(-3.175,-12.065) Y9(-1.905,-12.065) Y10(-0.635,-12.065) Y11(0.635,-12.065) Y12(1.905,-12.065) Y13(3.175,-12.065) Y14(4.445,-12.065) Y15(5.715,-12.065) Y16(6.985,-12.065) Y17(8.255,-12.065) Y18(9.525,-12.065) Y19(10.795,-12.065) Y20(12.065,-12.065)
Top Overlay:
  circle w0.25: c-14.15,12.065 r0.125
  region: -12.5,13.5 -13.5,12.5 -13.5,13.5
  lines w0.2: -13.5,12.5 -12.5,13.5 ; -13.5,-13.5 13.5,-13.5 13.5,13.5 -13.5,13.5 -13.5,-13.5
Mechanical 13:
  lines w0.1: -13.5,-13.5 13.5,-13.5 13.5,13.5 -13.5,13.5 -13.5,-13.5
Mechanical 15:
  lines w0.1: -0.5,0 0.5,0 ; 0,-0.5 0,0.5 ; -14.5,-14.5 14.5,-14.5 14.5,14.5 -14.5,14.5 -14.5,-14.5
3D body: height 2.55, standoff 0, extent -13.5,-13.5 13.5,13.5

## BG352 [mm] "352-Ball Metal Ball Grid Array (BG352)"
height 1.7
pads (352):
  round 0.6 smd: A1(-15.875,15.875) A2(-14.605,15.875) A3(-13.335,15.875) A4(-12.065,15.875) A5(-10.795,15.875) A6(-9.525,15.875) A7(-8.255,15.875) A8(-6.985,15.875) A9(-5.715,15.875) A10(-4.445,15.875) A11(-3.175,15.875) A12(-1.905,15.875) A13(-0.635,15.875) A14(0.635,15.875) A15(1.905,15.875) A16(3.175,15.875) A17(4.445,15.875) A18(5.715,15.875) A19(6.985,15.875) A20(8.255,15.875) A21(9.525,15.875) A22(10.795,15.875) A23(12.065,15.875) A24(13.335,15.875) A25(14.605,15.875) A26(15.875,15.875) AA1(-15.875,-9.525) AA2(-14.605,-9.525) AA3(-13.335,-9.525) AA4(-12.065,-9.525) AA23(12.065,-9.525) AA24(13.335,-9.525) AA25(14.605,-9.525) AA26(15.875,-9.525) AB1(-15.875,-10.795) AB2(-14.605,-10.795) AB3(-13.335,-10.795) AB4(-12.065,-10.795) AB23(12.065,-10.795) AB24(13.335,-10.795) AB25(14.605,-10.795) AB26(15.875,-10.795) AC1(-15.875,-12.065) AC2(-14.605,-12.065) AC3(-13.335,-12.065) AC4(-12.065,-12.065) AC5(-10.795,-12.065) AC6(-9.525,-12.065) AC7(-8.255,-12.065) AC8(-6.985,-12.065) AC9(-5.715,-12.065) AC10(-4.445,-12.065) AC11(-3.175,-12.065) AC12(-1.905,-12.065) AC13(-0.635,-12.065) AC14(0.635,-12.065) AC15(1.905,-12.065) AC16(3.175,-12.065) AC17(4.445,-12.065) AC18(5.715,-12.065) AC19(6.985,-12.065) AC20(8.255,-12.065) AC21(9.525,-12.065) AC22(10.795,-12.065) AC23(12.065,-12.065) AC24(13.335,-12.065) AC25(14.605,-12.065) AC26(15.875,-12.065) AD1(-15.875,-13.335) AD2(-14.605,-13.335) AD3(-13.335,-13.335) AD4(-12.065,-13.335) AD5(-10.795,-13.335) AD6(-9.525,-13.335) AD7(-8.255,-13.335) AD8(-6.985,-13.335) AD9(-5.715,-13.335) AD10(-4.445,-13.335) AD11(-3.175,-13.335) AD12(-1.905,-13.335) AD13(-0.635,-13.335) AD14(0.635,-13.335) AD15(1.905,-13.335) AD16(3.175,-13.335) AD17(4.445,-13.335) AD18(5.715,-13.335) AD19(6.985,-13.335) AD20(8.255,-13.335) AD21(9.525,-13.335) AD22(10.795,-13.335) AD23(12.065,-13.335) AD24(13.335,-13.335) AD25(14.605,-13.335) AD26(15.875,-13.335) AE1(-15.875,-14.605) AE2(-14.605,-14.605) AE3(-13.335,-14.605) AE4(-12.065,-14.605) AE5(-10.795,-14.605) AE6(-9.525,-14.605) AE7(-8.255,-14.605) AE8(-6.985,-14.605) AE9(-5.715,-14.605) AE10(-4.445,-14.605) AE11(-3.175,-14.605) AE12(-1.905,-14.605) AE13(-0.635,-14.605) AE14(0.635,-14.605) AE15(1.905,-14.605) AE16(3.175,-14.605) AE17(4.445,-14.605) AE18(5.715,-14.605) AE19(6.985,-14.605) AE20(8.255,-14.605) AE21(9.525,-14.605) AE22(10.795,-14.605) AE23(12.065,-14.605) AE24(13.335,-14.605) AE25(14.605,-14.605) AE26(15.875,-14.605) AF1(-15.875,-15.875) AF2(-14.605,-15.875) AF3(-13.335,-15.875) AF4(-12.065,-15.875) AF5(-10.795,-15.875) AF6(-9.525,-15.875) AF7(-8.255,-15.875) AF8(-6.985,-15.875) AF9(-5.715,-15.875) AF10(-4.445,-15.875) AF11(-3.175,-15.875) AF12(-1.905,-15.875) AF13(-0.635,-15.875) AF14(0.635,-15.875) AF15(1.905,-15.875) AF16(3.175,-15.875) AF17(4.445,-15.875) AF18(5.715,-15.875) AF19(6.985,-15.875) AF20(8.255,-15.875) AF21(9.525,-15.875) AF22(10.795,-15.875) AF23(12.065,-15.875) AF24(13.335,-15.875) AF25(14.605,-15.875) AF26(15.875,-15.875) B1(-15.875,14.605) B2(-14.605,14.605) B3(-13.335,14.605) B4(-12.065,14.605) B5(-10.795,14.605) B6(-9.525,14.605) B7(-8.255,14.605) B8(-6.985,14.605) B9(-5.715,14.605) B10(-4.445,14.605) B11(-3.175,14.605) B12(-1.905,14.605) B13(-0.635,14.605) B14(0.635,14.605) B15(1.905,14.605) B16(3.175,14.605) B17(4.445,14.605) B18(5.715,14.605) B19(6.985,14.605) B20(8.255,14.605) B21(9.525,14.605) B22(10.795,14.605) B23(12.065,14.605) B24(13.335,14.605) B25(14.605,14.605) B26(15.875,14.605) C1(-15.875,13.335) C2(-14.605,13.335) C3(-13.335,13.335) C4(-12.065,13.335) C5(-10.795,13.335) C6(-9.525,13.335) C7(-8.255,13.335) C8(-6.985,13.335) C9(-5.715,13.335) C10(-4.445,13.335) C11(-3.175,13.335) C12(-1.905,13.335) C13(-0.635,13.335) C14(0.635,13.335) C15(1.905,13.335) C16(3.175,13.335) C17(4.445,13.335) C18(5.715,13.335) C19(6.985,13.335) C20(8.255,13.335) C21(9.525,13.335) C22(10.795,13.335) C23(12.065,13.335) C24(13.335,13.335) C25(14.605,13.335) C26(15.875,13.335) D1(-15.875,12.065) D2(-14.605,12.065) D3(-13.335,12.065) D4(-12.065,12.065) D5(-10.795,12.065) D6(-9.525,12.065) D7(-8.255,12.065) D8(-6.985,12.065) D9(-5.715,12.065) D10(-4.445,12.065) D11(-3.175,12.065) D12(-1.905,12.065) D13(-0.635,12.065) D14(0.635,12.065) D15(1.905,12.065) D16(3.175,12.065) D17(4.445,12.065) D18(5.715,12.065) D19(6.985,12.065) D20(8.255,12.065) D21(9.525,12.065) D22(10.795,12.065) D23(12.065,12.065) D24(13.335,12.065) D25(14.605,12.065) D26(15.875,12.065) E1(-15.875,10.795) E2(-14.605,10.795) E3(-13.335,10.795) E4(-12.065,10.795) E23(12.065,10.795) E24(13.335,10.795) E25(14.605,10.795) E26(15.875,10.795) F1(-15.875,9.525) F2(-14.605,9.525) F3(-13.335,9.525) F4(-12.065,9.525) F23(12.065,9.525) F24(13.335,9.525) F25(14.605,9.525) F26(15.875,9.525) G1(-15.875,8.255) G2(-14.605,8.255) G3(-13.335,8.255) G4(-12.065,8.255) G23(12.065,8.255) G24(13.335,8.255) G25(14.605,8.255) G26(15.875,8.255) H1(-15.875,6.985) H2(-14.605,6.985) H3(-13.335,6.985) H4(-12.065,6.985) H23(12.065,6.985) H24(13.335,6.985) H25(14.605,6.985) H26(15.875,6.985) J1(-15.875,5.715) J2(-14.605,5.715) J3(-13.335,5.715) J4(-12.065,5.715) J23(12.065,5.715) J24(13.335,5.715) J25(14.605,5.715) J26(15.875,5.715) K1(-15.875,4.445) K2(-14.605,4.445) K3(-13.335,4.445) K4(-12.065,4.445) K23(12.065,4.445) K24(13.335,4.445) K25(14.605,4.445) K26(15.875,4.445) L1(-15.875,3.175) L2(-14.605,3.175) L3(-13.335,3.175) L4(-12.065,3.175) L23(12.065,3.175) L24(13.335,3.175) L25(14.605,3.175) L26(15.875,3.175) M1(-15.875,1.905) M2(-14.605,1.905) M3(-13.335,1.905) M4(-12.065,1.905) M23(12.065,1.905) M24(13.335,1.905) M25(14.605,1.905) M26(15.875,1.905) N1(-15.875,0.635) N2(-14.605,0.635) N3(-13.335,0.635) N4(-12.065,0.635) N23(12.065,0.635) N24(13.335,0.635) N25(14.605,0.635) N26(15.875,0.635) P1(-15.875,-0.635) P2(-14.605,-0.635) P3(-13.335,-0.635) P4(-12.065,-0.635) P23(12.065,-0.635) P24(13.335,-0.635) P25(14.605,-0.635) P26(15.875,-0.635) R1(-15.875,-1.905) R2(-14.605,-1.905) R3(-13.335,-1.905) R4(-12.065,-1.905) R23(12.065,-1.905) R24(13.335,-1.905) R25(14.605,-1.905) R26(15.875,-1.905) T1(-15.875,-3.175) T2(-14.605,-3.175) T3(-13.335,-3.175) T4(-12.065,-3.175) T23(12.065,-3.175) T24(13.335,-3.175) T25(14.605,-3.175) T26(15.875,-3.175) U1(-15.875,-4.445) U2(-14.605,-4.445) U3(-13.335,-4.445) U4(-12.065,-4.445) U23(12.065,-4.445) U24(13.335,-4.445) U25(14.605,-4.445) U26(15.875,-4.445) V1(-15.875,-5.715) V2(-14.605,-5.715) V3(-13.335,-5.715) V4(-12.065,-5.715) V23(12.065,-5.715) V24(13.335,-5.715) V25(14.605,-5.715) V26(15.875,-5.715) W1(-15.875,-6.985) W2(-14.605,-6.985) W3(-13.335,-6.985) W4(-12.065,-6.985) W23(12.065,-6.985) W24(13.335,-6.985) W25(14.605,-6.985) W26(15.875,-6.985) Y1(-15.875,-8.255) Y2(-14.605,-8.255) Y3(-13.335,-8.255) Y4(-12.065,-8.255) Y23(12.065,-8.255) Y24(13.335,-8.255) Y25(14.605,-8.255) Y26(15.875,-8.255)
Top Overlay:
  circle w0.25: c-18.15,15.875 r0.125
  region: -16.5,17.5 -17.5,16.5 -17.5,17.5
  lines w0.2: -17.5,16.5 -16.5,17.5 ; -17.5,-17.5 17.5,-17.5 17.5,17.5 -17.5,17.5 -17.5,-17.5
Mechanical 13:
  lines w0.1: -17.5,-17.5 17.5,-17.5 17.5,17.5 -17.5,17.5 -17.5,-17.5
Mechanical 15:
  lines w0.1: -0.5,0 0.5,0 ; 0,-0.5 0,0.5 ; -18.5,-18.5 18.5,-18.5 18.5,18.5 -18.5,18.5 -18.5,-18.5
3D body: height 1.7, standoff 0, extent -17.5,-17.5 17.5,17.5

## BG388 [mm] "388-Ball Plastic Ball Grid Array (BG388)"
height 2.87
pads (388):
  round 0.6 smd: A1(-15.875,15.875) A2(-14.605,15.875) A3(-13.335,15.875) A4(-12.065,15.875) A5(-10.795,15.875) A6(-9.525,15.875) A7(-8.255,15.875) A8(-6.985,15.875) A9(-5.715,15.875) A10(-4.445,15.875) A11(-3.175,15.875) A12(-1.905,15.875) A13(-0.635,15.875) A14(0.635,15.875) A15(1.905,15.875) A16(3.175,15.875) A17(4.445,15.875) A18(5.715,15.875) A19(6.985,15.875) A20(8.255,15.875) A21(9.525,15.875) A22(10.795,15.875) A23(12.065,15.875) A24(13.335,15.875) A25(14.605,15.875) A26(15.875,15.875) AA1(-15.875,-9.525) AA2(-14.605,-9.525) AA3(-13.335,-9.525) AA4(-12.065,-9.525) AA23(12.065,-9.525) AA24(13.335,-9.525) AA25(14.605,-9.525) AA26(15.875,-9.525) AB1(-15.875,-10.795) AB2(-14.605,-10.795) AB3(-13.335,-10.795) AB4(-12.065,-10.795) AB23(12.065,-10.795) AB24(13.335,-10.795) AB25(14.605,-10.795) AB26(15.875,-10.795) AC1(-15.875,-12.065) AC2(-14.605,-12.065) AC3(-13.335,-12.065) AC4(-12.065,-12.065) AC5(-10.795,-12.065) AC6(-9.525,-12.065) AC7(-8.255,-12.065) AC8(-6.985,-12.065) AC9(-5.715,-12.065) AC10(-4.445,-12.065) AC11(-3.175,-12.065) AC12(-1.905,-12.065) AC13(-0.635,-12.065) AC14(0.635,-12.065) AC15(1.905,-12.065) AC16(3.175,-12.065) AC17(4.445,-12.065) AC18(5.715,-12.065) AC19(6.985,-12.065) AC20(8.255,-12.065) AC21(9.525,-12.065) AC22(10.795,-12.065) AC23(12.065,-12.065) AC24(13.335,-12.065) AC25(14.605,-12.065) AC26(15.875,-12.065) AD1(-15.875,-13.335) AD2(-14.605,-13.335) AD3(-13.335,-13.335) AD4(-12.065,-13.335) AD5(-10.795,-13.335) AD6(-9.525,-13.335) AD7(-8.255,-13.335) AD8(-6.985,-13.335) AD9(-5.715,-13.335) AD10(-4.445,-13.335) AD11(-3.175,-13.335) AD12(-1.905,-13.335) AD13(-0.635,-13.335) AD14(0.635,-13.335) AD15(1.905,-13.335) AD16(3.175,-13.335) AD17(4.445,-13.335) AD18(5.715,-13.335) AD19(6.985,-13.335) AD20(8.255,-13.335) AD21(9.525,-13.335) AD22(10.795,-13.335) AD23(12.065,-13.335) AD24(13.335,-13.335) AD25(14.605,-13.335) AD26(15.875,-13.335) AE1(-15.875,-14.605) AE2(-14.605,-14.605) AE3(-13.335,-14.605) AE4(-12.065,-14.605) AE5(-10.795,-14.605) AE6(-9.525,-14.605) AE7(-8.255,-14.605) AE8(-6.985,-14.605) AE9(-5.715,-14.605) AE10(-4.445,-14.605) AE11(-3.175,-14.605) AE12(-1.905,-14.605) AE13(-0.635,-14.605) AE14(0.635,-14.605) AE15(1.905,-14.605) AE16(3.175,-14.605) AE17(4.445,-14.605) AE18(5.715,-14.605) AE19(6.985,-14.605) AE20(8.255,-14.605) AE21(9.525,-14.605) AE22(10.795,-14.605) AE23(12.065,-14.605) AE24(13.335,-14.605) AE25(14.605,-14.605) AE26(15.875,-14.605) AF1(-15.875,-15.875) AF2(-14.605,-15.875) AF3(-13.335,-15.875) AF4(-12.065,-15.875) AF5(-10.795,-15.875) AF6(-9.525,-15.875) AF7(-8.255,-15.875) AF8(-6.985,-15.875) AF9(-5.715,-15.875) AF10(-4.445,-15.875) AF11(-3.175,-15.875) AF12(-1.905,-15.875) AF13(-0.635,-15.875) AF14(0.635,-15.875) AF15(1.905,-15.875) AF16(3.175,-15.875) AF17(4.445,-15.875) AF18(5.715,-15.875) AF19(6.985,-15.875) AF20(8.255,-15.875) AF21(9.525,-15.875) AF22(10.795,-15.875) AF23(12.065,-15.875) AF24(13.335,-15.875) AF25(14.605,-15.875) AF26(15.875,-15.875) B1(-15.875,14.605) B2(-14.605,14.605) B3(-13.335,14.605) B4(-12.065,14.605) B5(-10.795,14.605) B6(-9.525,14.605) B7(-8.255,14.605) B8(-6.985,14.605) B9(-5.715,14.605) B10(-4.445,14.605) B11(-3.175,14.605) B12(-1.905,14.605) B13(-0.635,14.605) B14(0.635,14.605) B15(1.905,14.605) B16(3.175,14.605) B17(4.445,14.605) B18(5.715,14.605) B19(6.985,14.605) B20(8.255,14.605) B21(9.525,14.605) B22(10.795,14.605) B23(12.065,14.605) B24(13.335,14.605) B25(14.605,14.605) B26(15.875,14.605) C1(-15.875,13.335) C2(-14.605,13.335) C3(-13.335,13.335) C4(-12.065,13.335) C5(-10.795,13.335) C6(-9.525,13.335) C7(-8.255,13.335) C8(-6.985,13.335) C9(-5.715,13.335) C10(-4.445,13.335) C11(-3.175,13.335) C12(-1.905,13.335) C13(-0.635,13.335) C14(0.635,13.335) C15(1.905,13.335) C16(3.175,13.335) C17(4.445,13.335) C18(5.715,13.335) C19(6.985,13.335) C20(8.255,13.335) C21(9.525,13.335) C22(10.795,13.335) C23(12.065,13.335) C24(13.335,13.335) C25(14.605,13.335) C26(15.875,13.335) D1(-15.875,12.065) D2(-14.605,12.065) D3(-13.335,12.065) D4(-12.065,12.065) D5(-10.795,12.065) D6(-9.525,12.065) D7(-8.255,12.065) D8(-6.985,12.065) D9(-5.715,12.065) D10(-4.445,12.065) D11(-3.175,12.065) D12(-1.905,12.065) D13(-0.635,12.065) D14(0.635,12.065) D15(1.905,12.065) D16(3.175,12.065) D17(4.445,12.065) D18(5.715,12.065) D19(6.985,12.065) D20(8.255,12.065) D21(9.525,12.065) D22(10.795,12.065) D23(12.065,12.065) D24(13.335,12.065) D25(14.605,12.065) D26(15.875,12.065) E1(-15.875,10.795) E2(-14.605,10.795) E3(-13.335,10.795) E4(-12.065,10.795) E23(12.065,10.795) E24(13.335,10.795) E25(14.605,10.795) E26(15.875,10.795) F1(-15.875,9.525) F2(-14.605,9.525) F3(-13.335,9.525) F4(-12.065,9.525) F23(12.065,9.525) F24(13.335,9.525) F25(14.605,9.525) F26(15.875,9.525) G1(-15.875,8.255) G2(-14.605,8.255) G3(-13.335,8.255) G4(-12.065,8.255) G23(12.065,8.255) G24(13.335,8.255) G25(14.605,8.255) G26(15.875,8.255) H1(-15.875,6.985) H2(-14.605,6.985) H3(-13.335,6.985) H4(-12.065,6.985) H23(12.065,6.985) H24(13.335,6.985) H25(14.605,6.985) H26(15.875,6.985) J1(-15.875,5.715) J2(-14.605,5.715) J3(-13.335,5.715) J4(-12.065,5.715) J23(12.065,5.715) J24(13.335,5.715) J25(14.605,5.715) J26(15.875,5.715) K1(-15.875,4.445) K2(-14.605,4.445) K3(-13.335,4.445) K4(-12.065,4.445) K23(12.065,4.445) K24(13.335,4.445) K25(14.605,4.445) K26(15.875,4.445) L1(-15.875,3.175) L2(-14.605,3.175) L3(-13.335,3.175) L4(-12.065,3.175) L11(-3.175,3.175) L12(-1.905,3.175) L13(-0.635,3.175) L14(0.635,3.175) L15(1.905,3.175) L16(3.175,3.175) L23(12.065,3.175) L24(13.335,3.175) L25(14.605,3.175) L26(15.875,3.175) M1(-15.875,1.905) M2(-14.605,1.905) M3(-13.335,1.905) M4(-12.065,1.905) M11(-3.175,1.905) M12(-1.905,1.905) M13(-0.635,1.905) M14(0.635,1.905) M15(1.905,1.905) M16(3.175,1.905) M23(12.065,1.905) M24(13.335,1.905) M25(14.605,1.905) M26(15.875,1.905) N1(-15.875,0.635) N2(-14.605,0.635) N3(-13.335,0.635) N4(-12.065,0.635) N11(-3.175,0.635) N12(-1.905,0.635) N13(-0.635,0.635) N14(0.635,0.635) N15(1.905,0.635) N16(3.175,0.635) N23(12.065,0.635) N24(13.335,0.635) N25(14.605,0.635) N26(15.875,0.635) P1(-15.875,-0.635) P2(-14.605,-0.635) P3(-13.335,-0.635) P4(-12.065,-0.635) P11(-3.175,-0.635) P12(-1.905,-0.635) P13(-0.635,-0.635) P14(0.635,-0.635) P15(1.905,-0.635) P16(3.175,-0.635) P23(12.065,-0.635) P24(13.335,-0.635) P25(14.605,-0.635) P26(15.875,-0.635) R1(-15.875,-1.905) R2(-14.605,-1.905) R3(-13.335,-1.905) R4(-12.065,-1.905) R11(-3.175,-1.905) R12(-1.905,-1.905) R13(-0.635,-1.905) R14(0.635,-1.905) R15(1.905,-1.905) R16(3.175,-1.905) R23(12.065,-1.905) R24(13.335,-1.905) R25(14.605,-1.905) R26(15.875,-1.905) T1(-15.875,-3.175) T2(-14.605,-3.175) T3(-13.335,-3.175) T4(-12.065,-3.175) T11(-3.175,-3.175) T12(-1.905,-3.175) T13(-0.635,-3.175) T14(0.635,-3.175) T15(1.905,-3.175) T16(3.175,-3.175) T23(12.065,-3.175) T24(13.335,-3.175) T25(14.605,-3.175) T26(15.875,-3.175) U1(-15.875,-4.445) U2(-14.605,-4.445) U3(-13.335,-4.445) U4(-12.065,-4.445) U23(12.065,-4.445) U24(13.335,-4.445) U25(14.605,-4.445) U26(15.875,-4.445) V1(-15.875,-5.715) V2(-14.605,-5.715) V3(-13.335,-5.715) V4(-12.065,-5.715) V23(12.065,-5.715) V24(13.335,-5.715) V25(14.605,-5.715) V26(15.875,-5.715) W1(-15.875,-6.985) W2(-14.605,-6.985) W3(-13.335,-6.985) W4(-12.065,-6.985) W23(12.065,-6.985) W24(13.335,-6.985) W25(14.605,-6.985) W26(15.875,-6.985) Y1(-15.875,-8.255) Y2(-14.605,-8.255) Y3(-13.335,-8.255) Y4(-12.065,-8.255) Y23(12.065,-8.255) Y24(13.335,-8.255) Y25(14.605,-8.255) Y26(15.875,-8.255)
Top Overlay:
  circle w0.25: c-18.15,15.875 r0.125
  region: -16.5,17.5 -17.5,16.5 -17.5,17.5
  lines w0.2: -17.5,16.5 -16.5,17.5 ; -17.5,-17.5 -17.5,17.5 17.5,17.5 17.5,-17.5 -17.5,-17.5
Mechanical 13:
  lines w0.1: -17.5,-17.5 -17.5,17.5 17.5,17.5 17.5,-17.5 -17.5,-17.5
Mechanical 15:
  lines w0.1: -0.5,0 0.5,0 ; 0,-0.5 0,0.5 ; -18.5,-18.5 -18.5,18.5 18.5,18.5 18.5,-18.5 -18.5,-18.5
3D body: height 2.87, standoff 0, extent -17.5,-17.5 17.5,17.5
